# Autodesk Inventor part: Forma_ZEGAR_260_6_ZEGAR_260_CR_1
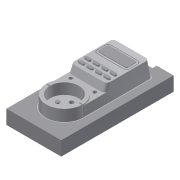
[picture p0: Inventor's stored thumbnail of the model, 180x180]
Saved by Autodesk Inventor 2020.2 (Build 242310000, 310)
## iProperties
Created: 2015-01
Part Number: Forma_ZEGAR_260_6_ZEGAR_260_CR_1
Material: Ogólny
Document SubType Name: Modeling
Designer: F.Stasiak
Density: 1 g/cm^3
Appearance: Domyślna
Catalog Web Link: www.expertbooks.pl
Manager: www.cadconsulting.pl
Company: Fabian Stasiak CAD Consulting
Author: F.Stasiak
Subject: Zbiór ćwiczeń. Autodesk Inventor 2020. Kurs Professional
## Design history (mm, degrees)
node "Forma_ZEGAR_260_4_ZEGAR_260_CR_Base"
feature "Bryła1::Forma_ZEGAR_260_4_ZEGAR_260_CR_Base"
tag "Bryła wyprowadzona1"
node "Bryła1"
feature "Forma_ZEGAR_260_4_ZEGAR_260_CR_Base_Bodies"
